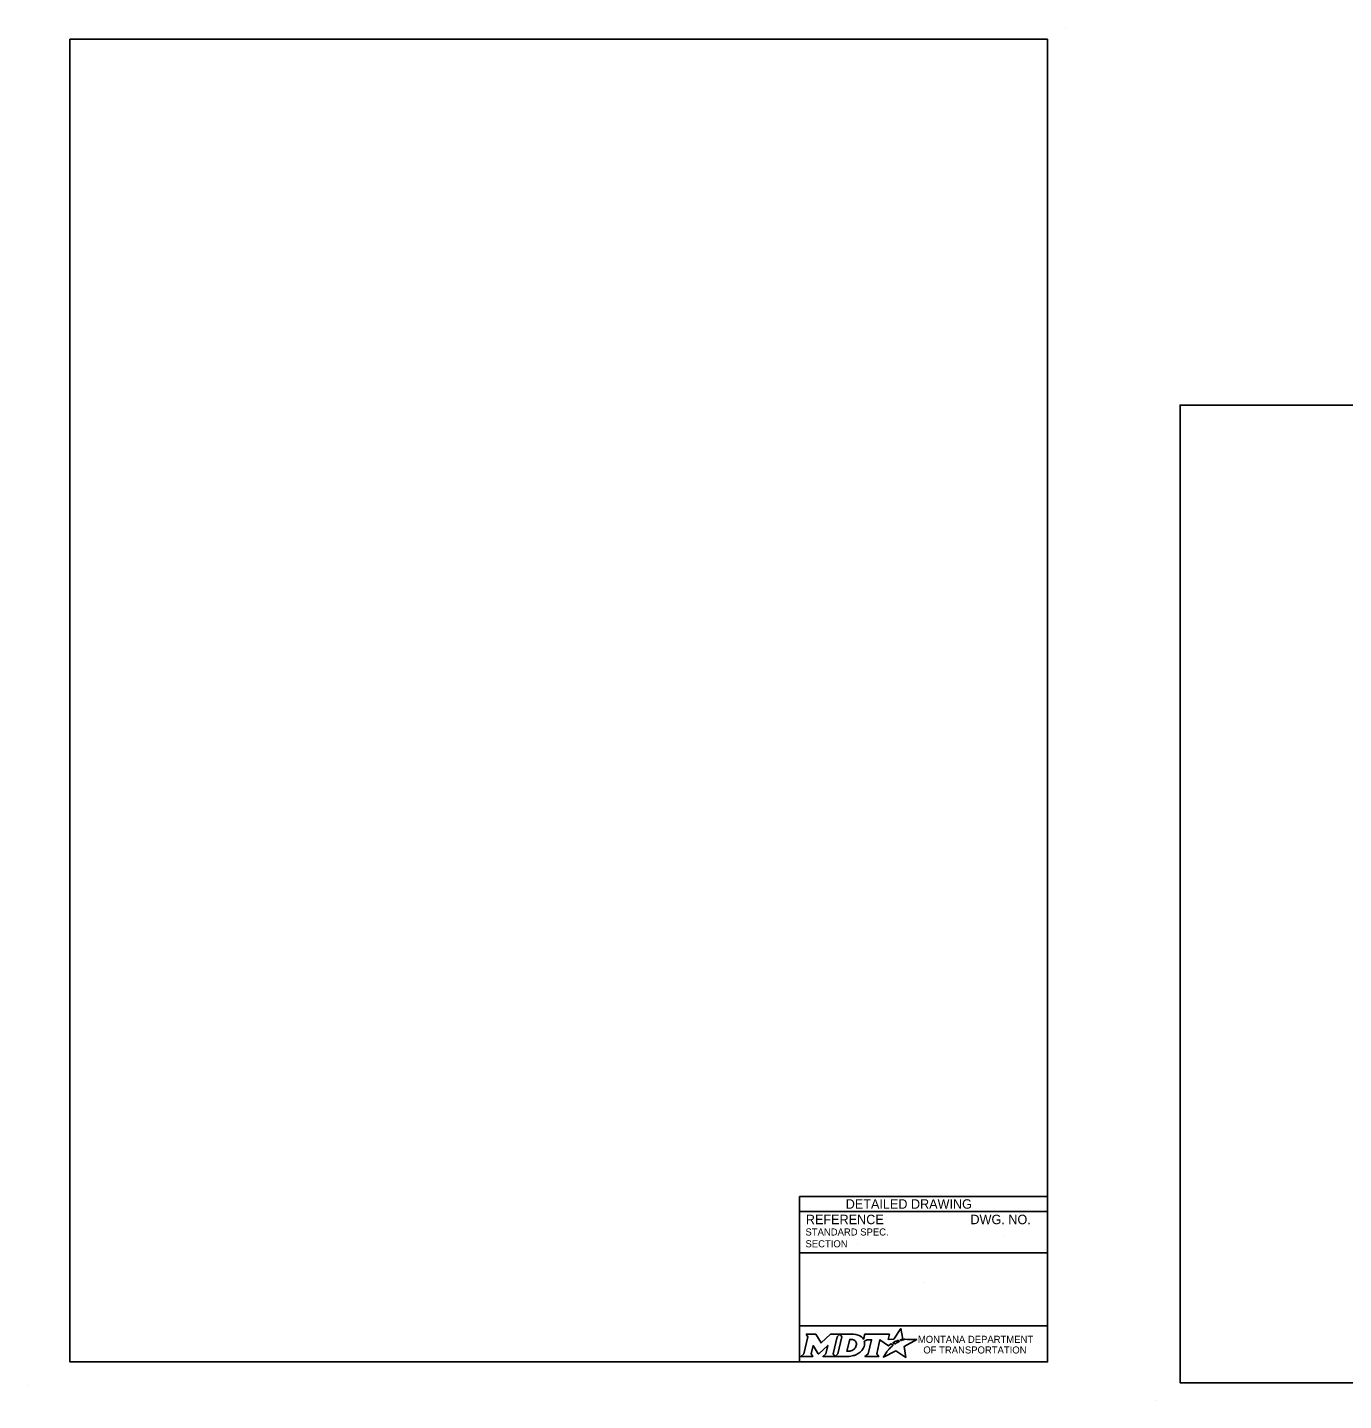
# Model space of a CAD drawing. Extents: x 49991.4 to 50021, y 49987.6 to 50011.4.
# Drawn here: x 49999.98 to 50011.12, y 49999.74 to 50011.36 of the extents above; entities that cross this region are included whole.
import ezdxf

# ---------------------------------------------------------------- set-up
doc = ezdxf.new("R2010")
doc.units = 0
doc.layers.add('Level 1', color=7, linetype='Continuous')
doc.layers.add('Level 2', color=7, linetype='Continuous')

msp = doc.modelspace()

# ---------------------------------------------------------------- linework, layer by layer
at = {"layer": 'Level 1'}
for p, q in [((50008.765, 50011.363), (50008.765, 50011.363)), ((49999.977, 49999.862), (49999.977, 49999.862)), ((50009.537, 49999.736), (50009.537, 49999.736))]:
    msp.add_line(p, q, dxfattribs=at)
for points in [[(50008.615, 50011.263), (50000.336, 50011.263), (50000.336, 50000.062), (50008.615, 50000.062)], [(50020.938, 50008.165), (50009.737, 50008.165), (50009.737, 49999.886), (50020.938, 49999.886)]]:
    msp.add_lwpolyline(points, close=True, dxfattribs=at)
at = {"layer": 'Level 2'}
for p, q in [((50008.615, 50001.462), (50006.515, 50001.462)), ((50006.515, 50001.462), (50006.515, 50000.062)), ((50008.615, 50001.337), (50006.515, 50001.337)), ((50007.009, 50001.063), (50007.009, 50001.063)), ((50008.251, 50001.122), (50008.251, 50001.122)), ((50008.615, 50000.987), (50006.515, 50000.987)), ((50007.565, 50000.738), (50007.565, 50000.738)), ((50008.615, 50000.369), (50006.515, 50000.369))]:
    msp.add_line(p, q, dxfattribs=at)
for points in [[(50007.377, 50000.245), (50007.367, 50000.25), (50007.378, 50000.253), (50007.39, 50000.255), (50007.373, 50000.345), (50007.313, 50000.254), (50007.266, 50000.253), (50007.276, 50000.297), (50007.067, 50000.297), (50007.057, 50000.255), (50007.051, 50000.263)], [(50006.57, 50000.297), (50006.584, 50000.274), (50006.551, 50000.131), (50006.525, 50000.108), (50006.627, 50000.108), (50006.613, 50000.131), (50006.629, 50000.201), (50006.673, 50000.132), (50006.678, 50000.132), (50006.753, 50000.202), (50006.737, 50000.13), (50006.712, 50000.108), (50006.814, 50000.108), (50006.8, 50000.132), (50006.833, 50000.274)], [(50006.833, 50000.274), (50006.859, 50000.297), (50006.776, 50000.297), (50006.697, 50000.224), (50006.652, 50000.297), (50006.57, 50000.297)], [(50006.972, 50000.297), (50006.859, 50000.297), (50006.873, 50000.275), (50006.839, 50000.131), (50006.814, 50000.108), (50006.925, 50000.108)], [(50006.996, 50000.211), (50006.995, 50000.203), (50006.992, 50000.193), (50006.988, 50000.185), (50006.982, 50000.178), (50006.976, 50000.171), (50006.968, 50000.164), (50006.959, 50000.16), (50006.95, 50000.156), (50006.941, 50000.154), (50006.932, 50000.153), (50006.916, 50000.153), (50006.94, 50000.253), (50006.956, 50000.253), (50006.963, 50000.252), (50006.971, 50000.25), (50006.977, 50000.247), (50006.983, 50000.243), (50006.988, 50000.238), (50006.992, 50000.232), (50006.995, 50000.226), (50006.996, 50000.218), (50006.996, 50000.215), (50006.996, 50000.211)], [(50007.064, 50000.238), (50007.088, 50000.251), (50007.125, 50000.251), (50007.097, 50000.131), (50007.069, 50000.108), (50007.185, 50000.108), (50007.168, 50000.131), (50007.196, 50000.251), (50007.268, 50000.2), (50007.289, 50000.215), (50007.309, 50000.204)], [(50007.253, 50000.148), (50007.237, 50000.124), (50007.233, 50000.116), (50007.227, 50000.107), (50007.225, 50000.103), (50007.33, 50000.156), (50007.414, 50000.101), (50007.401, 50000.194), (50007.508, 50000.252), (50007.458, 50000.253), (50007.428, 50000.253), (50007.407, 50000.254), (50007.401, 50000.252), (50007.396, 50000.251), (50007.387, 50000.249), (50007.377, 50000.245)], [(50007.327, 50000.217), (50007.324, 50000.215), (50007.306, 50000.225), (50007.316, 50000.231), (50007.32, 50000.233), (50007.329, 50000.237), (50007.335, 50000.239), (50007.343, 50000.243), (50007.35, 50000.245), (50007.362, 50000.238), (50007.358, 50000.236), (50007.353, 50000.233), (50007.349, 50000.231), (50007.344, 50000.228), (50007.342, 50000.227), (50007.339, 50000.225), (50007.337, 50000.224), (50007.334, 50000.222), (50007.332, 50000.221), (50007.329, 50000.219), (50007.327, 50000.217)], [(50006.97, 50000.116), (50006.979, 50000.118), (50006.992, 50000.124), (50007.012, 50000.135)], [(50007.267, 50000.164), (50007.267, 50000.164)]]:
    msp.add_lwpolyline(points, dxfattribs=at)
for centre, radius, start, end in [((50006.995, 50000.219), 0.0709, 339.5329, 15.8582), ((50006.951, 50000.236), 0.118, 300.9103, 339.1383)]:
    msp.add_arc(centre, radius, start, end, dxfattribs=at)
for centre, major_axis, ratio, start_param, end_param in [((50006.97, 50000.25), (0.0834, -0.0037), 0.568097, 0.61298, 1.570796), ((50007.026, 50000.257), (0.0361, -0.0295), 0.469099, 1.225588, 1.570796), ((50006.925, 50000.257), (0, 0.148), 0.987302, 3.139398, 3.456847), ((50007.26, 50000.156), (-0.00694, -0.00806), 0.008222, 0, 3.137361), ((50007.276, 50000.174), (-0.0098, -0.0102), 0.016458, 3.141593, 6.279097), ((50007.297, 50000.194), (-0.0112, -0.0097), 0.021651, 3.157348, 6.283185)]:
    msp.add_ellipse(centre, major_axis=major_axis, ratio=ratio, start_param=start_param, end_param=end_param, dxfattribs=at)

# ---------------------------------------------------------------- texts
for s, height, p in [('DETAILED DRAWING', 0.0799, (50006.906, 50001.36)), ('REFERENCE', 0.08, (50006.568, 50001.229)), ('DWG. NO.', 0.08, (50007.962, 50001.229)), ('STANDARD SPEC.', 0.06, (50006.565, 50001.133)), ('SECTION', 0.06, (50006.565, 50001.033))]:
    msp.add_text(s, height=height, dxfattribs=at).set_placement(p)
for s, p in [('MONTANA DEPARTMENT', (50007.517, 50000.224)), ('OF TRANSPORTATION', (50007.563, 50000.134))]:
    msp.add_text(s, height=0.06, rotation=360, dxfattribs=at).set_placement(p)

doc.saveas('drawing.dxf')
